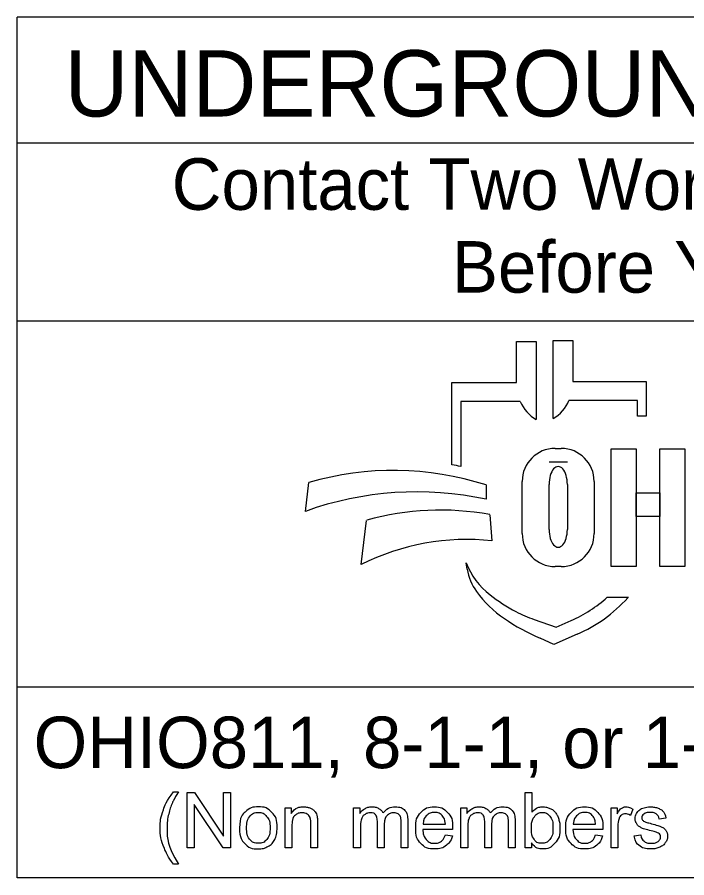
# Model space of a CAD drawing. Extents: x 0 to 68.9, y -26.1 to 22.
# Drawn here: x 2.805 to 4.623, y 2.143 to 4.48 of the extents above; entities that cross this region are included whole.
import ezdxf

# ---------------------------------------------------------------- set-up
doc = ezdxf.new("R2010")
doc.units = 0
doc.layers.add('SH_Data', color=7, linetype='Continuous')
doc.layers.add('SH_Text', color=7, linetype='Continuous')

msp = doc.modelspace()

# ---------------------------------------------------------------- linework, layer by layer
at = {"layer": 'SH_Data'}
for p, q in [((2.8045, 2.1428), (2.8045, 4.4803)), ((7.0545, 4.4803), (2.8045, 4.4803)), ((2.8045, 4.1387), (7.0545, 4.1387)), ((2.8045, 3.6553), (7.0545, 3.6553)), ((7.0545, 2.6607), (2.8045, 2.6607)), ((7.0545, 2.1428), (2.8045, 2.1428))]:
    msp.add_line(p, q, dxfattribs=at)
at = {"layer": 'SH_Text'}
for p, q in [((4.1606, 3.4883), (4.1606, 3.5998)), ((4.1606, 3.5998), (4.2142, 3.5998)), ((4.2142, 3.5998), (4.2142, 3.3877)), ((4.2599, 3.39), (4.2599, 3.6021)), ((4.2599, 3.6021), (4.3135, 3.6021)), ((4.3135, 3.6021), (4.3135, 3.4906)), ((3.9846, 3.2644), (3.9846, 3.4883)), ((3.9846, 3.4883), (4.1606, 3.4883)), ((4.3135, 3.4906), (4.5128, 3.4906)), ((4.5128, 3.4906), (4.5128, 3.3968)), ((4.0098, 3.4369), (4.0098, 3.26)), ((4.171, 3.4369), (4.0098, 3.4369)), ((4.4895, 3.4392), (4.3031, 3.4392)), ((4.4895, 3.3968), (4.4895, 3.4392)), ((4.5128, 3.3968), (4.4895, 3.3968)), ((4.2656, 3.3091), (4.2821, 3.3091)), ((4.2988, 3.2721), (4.249, 3.2721)), ((3.5872, 3.1381), (3.5966, 3.2162)), ((4.0779, 3.2097), (4.0779, 3.1709)), ((4.1761, 3.0776), (4.1761, 3.2196)), ((4.249, 3.089), (4.249, 3.2114)), ((4.2988, 3.2114), (4.2988, 3.089)), ((4.3716, 3.2196), (4.3716, 3.0776)), ((3.7391, 2.9936), (3.7537, 3.1137)), ((4.0879, 3.1291), (4.0941, 3.0582)), ((4.0268, 2.9807), (4.0237, 2.9986)), ((4.2821, 2.9882), (4.2656, 2.9882)), ((4.407, 2.9048), (4.4645, 2.9048)), ((4.2086, 2.8444), (4.268, 2.8239)), ((4.268, 2.8239), (4.3091, 2.8417)), ((4.262, 2.7769), (4.2247, 2.7934)), ((4.3253, 2.8044), (4.262, 2.7769))]:
    msp.add_line(p, q, dxfattribs=at)
for points in [[(4.418, 3.3081), (4.4859, 3.3081), (4.4859, 2.9881), (4.418, 2.9881)], [(4.5501, 3.3081), (4.6181, 3.3081), (4.6181, 2.9881), (4.5501, 2.9881)], [(4.4859, 3.1882), (4.5501, 3.1882), (4.5501, 3.1242), (4.4859, 3.1242)]]:
    msp.add_lwpolyline(points, close=True, dxfattribs=at)
for points in [[(3.2291, 2.3766), (3.2423, 2.3766)], [(3.2659, 2.2239), (3.2659, 2.3741), (3.2862, 2.3741), (3.3652, 2.2561), (3.3652, 2.3741), (3.3842, 2.3741), (3.3842, 2.2239), (3.3639, 2.2239), (3.2849, 2.3419), (3.2849, 2.2239), (3.2659, 2.2239)], [(4.2013, 2.2239), (4.1843, 2.2239), (4.1843, 2.3741), (4.2027, 2.3741), (4.2027, 2.3206)], [(3.5319, 2.2239), (3.5319, 2.3328), (3.5484, 2.3328), (3.5484, 2.3173)], [(3.7183, 2.2239), (3.7183, 2.3328), (3.7347, 2.3328), (3.7347, 2.3174)], [(4.0096, 2.2239), (4.0096, 2.3328), (4.0261, 2.3328), (4.0261, 2.3174)], [(4.4174, 2.2239), (4.4174, 2.3328), (4.434, 2.3328), (4.434, 2.3163)], [(4.4765, 2.3293), (4.47, 2.3122)], [(3.6202, 2.2908), (3.6202, 2.2239), (3.6018, 2.2239), (3.6018, 2.2901)], [(3.8013, 2.2871), (3.8013, 2.2239), (3.7829, 2.2239), (3.7829, 2.2946)], [(3.8658, 2.2986), (3.8658, 2.2239), (3.8474, 2.2239), (3.8474, 2.2924)], [(4.0927, 2.2871), (4.0927, 2.2239), (4.0743, 2.2239), (4.0743, 2.2946)], [(4.1572, 2.2986), (4.1572, 2.2239), (4.1387, 2.2239), (4.1387, 2.2924)], [(4.5664, 2.3046), (4.5483, 2.3022)], [(3.5503, 2.2833), (3.5503, 2.2239), (3.5319, 2.2239)], [(3.7367, 2.2803), (3.7367, 2.2239), (3.7183, 2.2239)], [(3.987, 2.2736), (3.9059, 2.2736)], [(3.9069, 2.2887), (3.9677, 2.2887)], [(4.0281, 2.2803), (4.0281, 2.2239), (4.0096, 2.2239)], [(4.395, 2.2736), (4.3138, 2.2736)], [(4.3149, 2.2887), (4.3756, 2.2887)], [(4.4358, 2.2809), (4.4358, 2.2239), (4.4174, 2.2239)], [(3.9674, 2.2591), (3.9865, 2.2567)], [(4.3754, 2.2591), (4.3945, 2.2567)], [(4.48, 2.2564), (4.4982, 2.2593)], [(4.2013, 2.2375), (4.2013, 2.2239)], [(3.2423, 2.1798), (3.2291, 2.1798)]]:
    msp.add_lwpolyline(points, dxfattribs=at)
for centre, radius, start, end in [((4.2623, 3.4736), 0.0985, 201.9296, 240.7469), ((4.2118, 3.476), 0.0985, 299.2531, 338.0704), ((4.2656, 3.2196), 0.0895, 90, 180), ((4.2821, 3.2196), 0.0895, 0, 90), ((3.8267, 2.4302), 0.8191, 72.1402, 106.3144), ((3.8565, 2.4554), 0.8191, 79.2074, 81.0007), ((3.8898, 2.2991), 0.8919, 77.8238, 109.8274), ((3.9537, 2.4094), 0.7322, 79.44, 105.8467), ((4.2656, 3.0776), 0.0895, 180, 270), ((4.2821, 3.0776), 0.0895, 270, 0), ((4.0257, 2.4262), 0.6357, 83.8248, 116.8021), ((4.2111, 3.0707), 0.2008, 201.0457, 232.5314), ((4.1681, 3.0048), 0.1433, 189.6817, 216.0884), ((4.3017, 3.1022), 0.3088, 216.0884, 235.7167), ((4.4036, 3.3219), 0.5173, 232.5314, 241.794), ((4.1657, 3.1722), 0.3602, 293.4582, 312.0712), ((4.1657, 3.1722), 0.401, 293.4582, 317.8286), ((4.3185, 3.1631), 0.3371, 241.794, 250.9821), ((4.4682, 3.3465), 0.6044, 235.7167, 246.2325)]:
    msp.add_arc(centre, radius, start, end, dxfattribs=at)
for centre, start_param, end_param in [((4.2739, 3.2114), 4.712389, 7.853982), ((4.2739, 3.089), 1.570796, 4.712389)]:
    msp.add_ellipse(centre, major_axis=(0, 0.0484), ratio=0.514403, start_param=start_param, end_param=end_param, dxfattribs=at)
for points in [[(3.2291, 2.1798), (3.2139, 2.199), (3.2033, 2.2248), (3.1928, 2.2506), (3.1928, 2.2783), (3.1928, 2.3026), (3.2006, 2.325), (3.2099, 2.3509), (3.2291, 2.3766)], [(3.2423, 2.3766), (3.2299, 2.3553), (3.226, 2.3462), (3.2197, 2.332), (3.2161, 2.3167), (3.2118, 2.2975), (3.2118, 2.2782), (3.2118, 2.2289), (3.2423, 2.1798)], [(3.4084, 2.2783), (3.4084, 2.3085), (3.4252, 2.3231), (3.4392, 2.3352), (3.4593, 2.3352), (3.4818, 2.3352), (3.496, 2.3205), (3.5102, 2.3058), (3.5102, 2.2799), (3.5102, 2.2589), (3.5039, 2.2469), (3.4976, 2.2348), (3.4856, 2.2282), (3.4736, 2.2215), (3.4593, 2.2215), (3.4365, 2.2215), (3.4224, 2.2362), (3.4084, 2.2508), (3.4084, 2.2783)], [(3.4274, 2.2783), (3.4274, 2.2574), (3.4365, 2.247), (3.4456, 2.2366), (3.4593, 2.2366), (3.473, 2.2366), (3.4821, 2.2471), (3.4912, 2.2575), (3.4912, 2.279), (3.4912, 2.2991), (3.4821, 2.3095), (3.4729, 2.3199), (3.4593, 2.3199), (3.4456, 2.3199), (3.4365, 2.3096), (3.4274, 2.2992), (3.4274, 2.2783)], [(3.5484, 2.3173), (3.5604, 2.3352), (3.583, 2.3352), (3.5929, 2.3352), (3.6011, 2.3316), (3.6094, 2.3281), (3.6134, 2.3224), (3.6175, 2.3166), (3.6192, 2.3087), (3.6202, 2.3036), (3.6202, 2.2908)], [(3.6018, 2.2901), (3.6018, 2.3013), (3.5996, 2.3069), (3.5975, 2.3125), (3.592, 2.3158), (3.5865, 2.3191), (3.5791, 2.3191), (3.5674, 2.3191), (3.5588, 2.3117), (3.5503, 2.3042), (3.5503, 2.2833)], [(3.7347, 2.3174), (3.7399, 2.3254), (3.7484, 2.3303), (3.7569, 2.3352), (3.7677, 2.3352), (3.7798, 2.3352), (3.7876, 2.3301), (3.7953, 2.3251), (3.7985, 2.3161), (3.8114, 2.3352), (3.8321, 2.3352), (3.8483, 2.3352), (3.8571, 2.3262), (3.8658, 2.3172), (3.8658, 2.2986)], [(3.7829, 2.2946), (3.7829, 2.3069), (3.7784, 2.313), (3.7739, 2.3191), (3.7636, 2.3191), (3.7559, 2.3191), (3.7492, 2.315), (3.7426, 2.311), (3.7397, 2.3031), (3.7367, 2.2952), (3.7367, 2.2803)], [(3.8474, 2.2924), (3.8474, 2.3035), (3.8456, 2.3083), (3.8438, 2.3132), (3.8391, 2.3162), (3.8343, 2.3191), (3.828, 2.3191), (3.8165, 2.3191), (3.8089, 2.3115), (3.8013, 2.3039), (3.8013, 2.2871)], [(3.9865, 2.2567), (3.982, 2.24), (3.9698, 2.2307), (3.9576, 2.2215), (3.9387, 2.2215), (3.9148, 2.2215), (3.9008, 2.2362), (3.8869, 2.2509), (3.8869, 2.2774), (3.8869, 2.3049), (3.901, 2.32), (3.9151, 2.3352), (3.9376, 2.3352), (3.9595, 2.3352), (3.9733, 2.3203), (3.9871, 2.3055), (3.9871, 2.2785), (3.9871, 2.2769), (3.987, 2.2736)], [(3.9677, 2.2887), (3.9664, 2.3025), (3.9607, 2.3094), (3.9519, 2.3201), (3.9378, 2.3201), (3.9251, 2.3201), (3.9165, 2.3115), (3.9078, 2.303), (3.9069, 2.2887)], [(4.0261, 2.3174), (4.0312, 2.3254), (4.0397, 2.3303), (4.0482, 2.3352), (4.0591, 2.3352), (4.0712, 2.3352), (4.0789, 2.3301), (4.0867, 2.3251), (4.0899, 2.3161), (4.1028, 2.3352), (4.1235, 2.3352), (4.1397, 2.3352), (4.1484, 2.3262), (4.1572, 2.3172), (4.1572, 2.2986)], [(4.0743, 2.2946), (4.0743, 2.3069), (4.0698, 2.313), (4.0653, 2.3191), (4.055, 2.3191), (4.0472, 2.3191), (4.0406, 2.315), (4.034, 2.311), (4.031, 2.3031), (4.0281, 2.2952), (4.0281, 2.2803)], [(4.1387, 2.2924), (4.1387, 2.3035), (4.1369, 2.3083), (4.1351, 2.3132), (4.1304, 2.3162), (4.1257, 2.3191), (4.1194, 2.3191), (4.1079, 2.3191), (4.1003, 2.3115), (4.0927, 2.3039), (4.0927, 2.2871)], [(4.2011, 2.2792), (4.2011, 2.2596), (4.2064, 2.2509), (4.2151, 2.2366), (4.2299, 2.2366), (4.242, 2.2366), (4.2508, 2.2471), (4.2596, 2.2576), (4.2596, 2.2784), (4.2596, 2.2998), (4.2512, 2.3099), (4.2427, 2.3201), (4.2308, 2.3201), (4.2187, 2.3201), (4.2099, 2.3096), (4.2011, 2.299), (4.2011, 2.2792)], [(4.2027, 2.3206), (4.2144, 2.3352), (4.2325, 2.3352), (4.2426, 2.3352), (4.2515, 2.3311), (4.2605, 2.3271), (4.2663, 2.3198), (4.272, 2.3124), (4.2753, 2.3021), (4.2786, 2.2918), (4.2786, 2.28), (4.2786, 2.252), (4.2648, 2.2368), (4.2509, 2.2215), (4.2316, 2.2215), (4.2123, 2.2215), (4.2013, 2.2375)], [(4.3945, 2.2567), (4.39, 2.24), (4.3778, 2.2307), (4.3656, 2.2215), (4.3467, 2.2215), (4.3228, 2.2215), (4.3088, 2.2362), (4.2948, 2.2509), (4.2948, 2.2774), (4.2948, 2.3049), (4.309, 2.32), (4.3231, 2.3352), (4.3456, 2.3352), (4.3674, 2.3352), (4.3813, 2.3203), (4.3951, 2.3055), (4.3951, 2.2785), (4.3951, 2.2769), (4.395, 2.2736)], [(4.3756, 2.2887), (4.3744, 2.3025), (4.3687, 2.3094), (4.3599, 2.3201), (4.3458, 2.3201), (4.3331, 2.3201), (4.3245, 2.3115), (4.3158, 2.303), (4.3149, 2.2887)], [(4.434, 2.3163), (4.4404, 2.3278), (4.4457, 2.3315), (4.4511, 2.3352), (4.4575, 2.3352), (4.4669, 2.3352), (4.4765, 2.3293)], [(4.47, 2.3122), (4.4633, 2.3162), (4.4566, 2.3162), (4.4505, 2.3162), (4.4457, 2.3125), (4.441, 2.3089), (4.4389, 2.3024), (4.4358, 2.2926), (4.4358, 2.2809)], [(4.5483, 2.3022), (4.5471, 2.3106), (4.5412, 2.3153), (4.5353, 2.3201), (4.5245, 2.3201), (4.5118, 2.3201), (4.5064, 2.3159), (4.501, 2.3116), (4.501, 2.306), (4.501, 2.3024), (4.5032, 2.2995), (4.5055, 2.2966), (4.5103, 2.2946), (4.5131, 2.2936), (4.5266, 2.2899), (4.5462, 2.2847), (4.5539, 2.2813), (4.5617, 2.278), (4.5661, 2.2717), (4.5705, 2.2653), (4.5705, 2.2559), (4.5705, 2.2467), (4.5652, 2.2386), (4.5598, 2.2304), (4.5496, 2.226), (4.5394, 2.2215), (4.5266, 2.2215), (4.5054, 2.2215), (4.4942, 2.2303), (4.4831, 2.2391), (4.48, 2.2564)], [(4.4982, 2.2593), (4.4998, 2.2483), (4.5068, 2.2425), (4.5138, 2.2366), (4.5265, 2.2366), (4.5392, 2.2366), (4.5454, 2.2418), (4.5515, 2.247), (4.5515, 2.254), (4.5515, 2.2602), (4.5461, 2.2638), (4.5423, 2.2663), (4.5272, 2.2701), (4.5069, 2.2752), (4.4991, 2.2789), (4.4912, 2.2827), (4.4872, 2.2893), (4.4831, 2.2959), (4.4831, 2.3038), (4.4831, 2.3111), (4.4864, 2.3173), (4.4898, 2.3235), (4.4955, 2.3276), (4.4998, 2.3308), (4.5073, 2.333), (4.5147, 2.3352), (4.5232, 2.3352), (4.5361, 2.3352), (4.5457, 2.3315), (4.5554, 2.3278), (4.5601, 2.3215), (4.5647, 2.3152), (4.5664, 2.3046)], [(3.9059, 2.2736), (3.9069, 2.2557), (3.916, 2.2462), (3.9251, 2.2366), (3.9387, 2.2366), (3.9489, 2.2366), (3.9561, 2.242), (3.9632, 2.2473), (3.9674, 2.2591)], [(4.3138, 2.2736), (4.3149, 2.2557), (4.324, 2.2462), (4.3331, 2.2366), (4.3467, 2.2366), (4.3569, 2.2366), (4.3641, 2.242), (4.3712, 2.2473), (4.3754, 2.2591)]]:
    msp.add_open_spline(points, degree=3, dxfattribs=at)

# ---------------------------------------------------------------- texts
for s, height, p in [('UNDERGROUND UTILITIES', 0.18, (2.9327, 4.2106)), ('Contact Two Working Days', 0.14, (3.2242, 3.9571)), ('Before You Dig', 0.14, (3.9854, 3.7321)), ('OHIO811, 8-1-1, or 1-800-362-2764', 0.14, (2.849, 2.4406))]:
    msp.add_text(s, height=height, dxfattribs=at).set_placement(p)

doc.saveas('drawing.dxf')
